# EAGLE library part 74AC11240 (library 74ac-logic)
Octal BUFFER/DRIVER
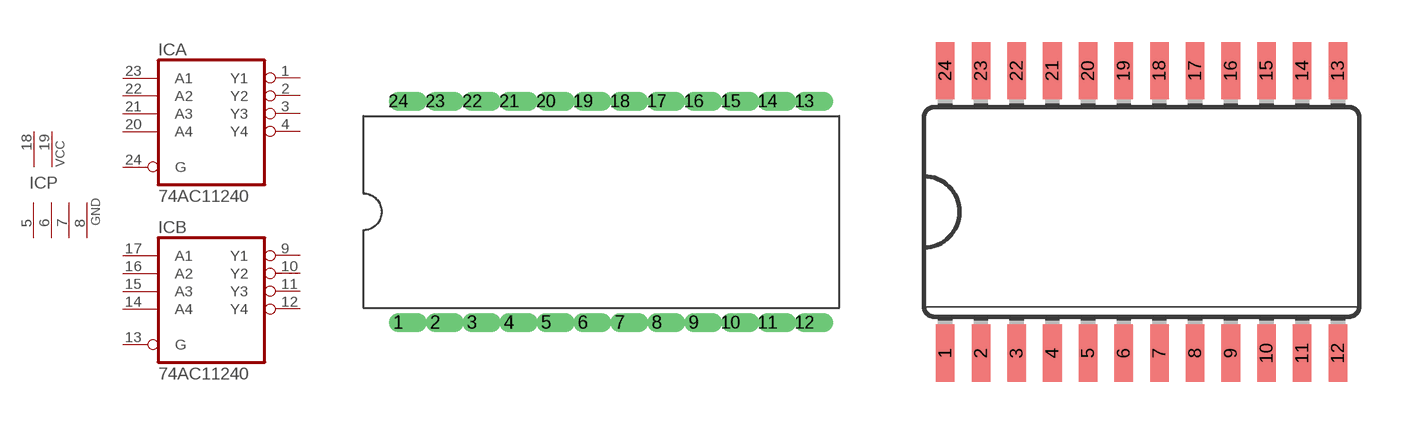
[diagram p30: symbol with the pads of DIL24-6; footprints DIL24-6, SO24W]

Designator prefix IC; gates A=7411240 B=7411240 P=2PWR4GND

## 74AC11240  [DIL24-6]
1  A:Y1  hiz
2  A:Y2  hiz
3  A:Y3  hiz
4  A:Y4  hiz
5  P:GND  pwr
6  P:GND  pwr
7  P:GND  pwr
8  P:GND  pwr
9  B:Y1  hiz
10  B:Y2  hiz
11  B:Y3  hiz
12  B:Y4  hiz
13  B:G  in
14  B:A4  in
15  B:A3  in
16  B:A2  in
17  B:A1  in
18  P:VCC  pwr
19  P:VCC  pwr
20  A:A4  in
21  A:A3  in
22  A:A2  in
23  A:A1  in
24  A:G  in

## 74AC11240D  [SO24W]
Pads as for DIL24-6

## Footprint DIL24-6 (pad centres in mm)
Dual In Line 0.6 inch
drill 0.813 offset: 1 -13.97,-7.62; 2 -11.43,-7.62; 3 -8.89,-7.62; 4 -6.35,-7.62; 5 -3.81,-7.62; 6 -1.27,-7.62; 7 1.27,-7.62; 8 3.81,-7.62; 9 6.35,-7.62; 10 8.89,-7.62; 11 11.43,-7.62; 12 13.97,-7.62; 13 13.97,7.62; 14 11.43,7.62; 15 8.89,7.62; 16 6.35,7.62; 17 3.81,7.62; 18 1.27,7.62; 19 -1.27,7.62; 20 -3.81,7.62; 21 -6.35,7.62; 22 -8.89,7.62; 23 -11.43,7.62; 24 -13.97,7.62

## Footprint SO24W (pad centres in mm)
Wide Small Outline package 300 mil
smd 0.66 x 2.032: 1 -6.985,-5.029; 2 -5.715,-5.029; 3 -4.445,-5.029; 4 -3.175,-5.029; 5 -1.905,-5.029; 6 -0.635,-5.029; 7 0.635,-5.029; 8 1.905,-5.029; 9 3.175,-5.029; 10 4.445,-5.029; 11 5.715,-5.029; 12 6.985,-5.029; 13 6.985,5.029; 14 5.715,5.029; 15 4.445,5.029; 16 3.175,5.029; 17 1.905,5.029; 18 0.635,5.029; 19 -0.635,5.029; 20 -1.905,5.029; 21 -3.175,5.029; 22 -4.445,5.029; 23 -5.715,5.029; 24 -6.985,5.029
